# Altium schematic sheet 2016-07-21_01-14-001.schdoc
size 331 x 152 mm; SheetNumber: 1; SheetTotal: 1
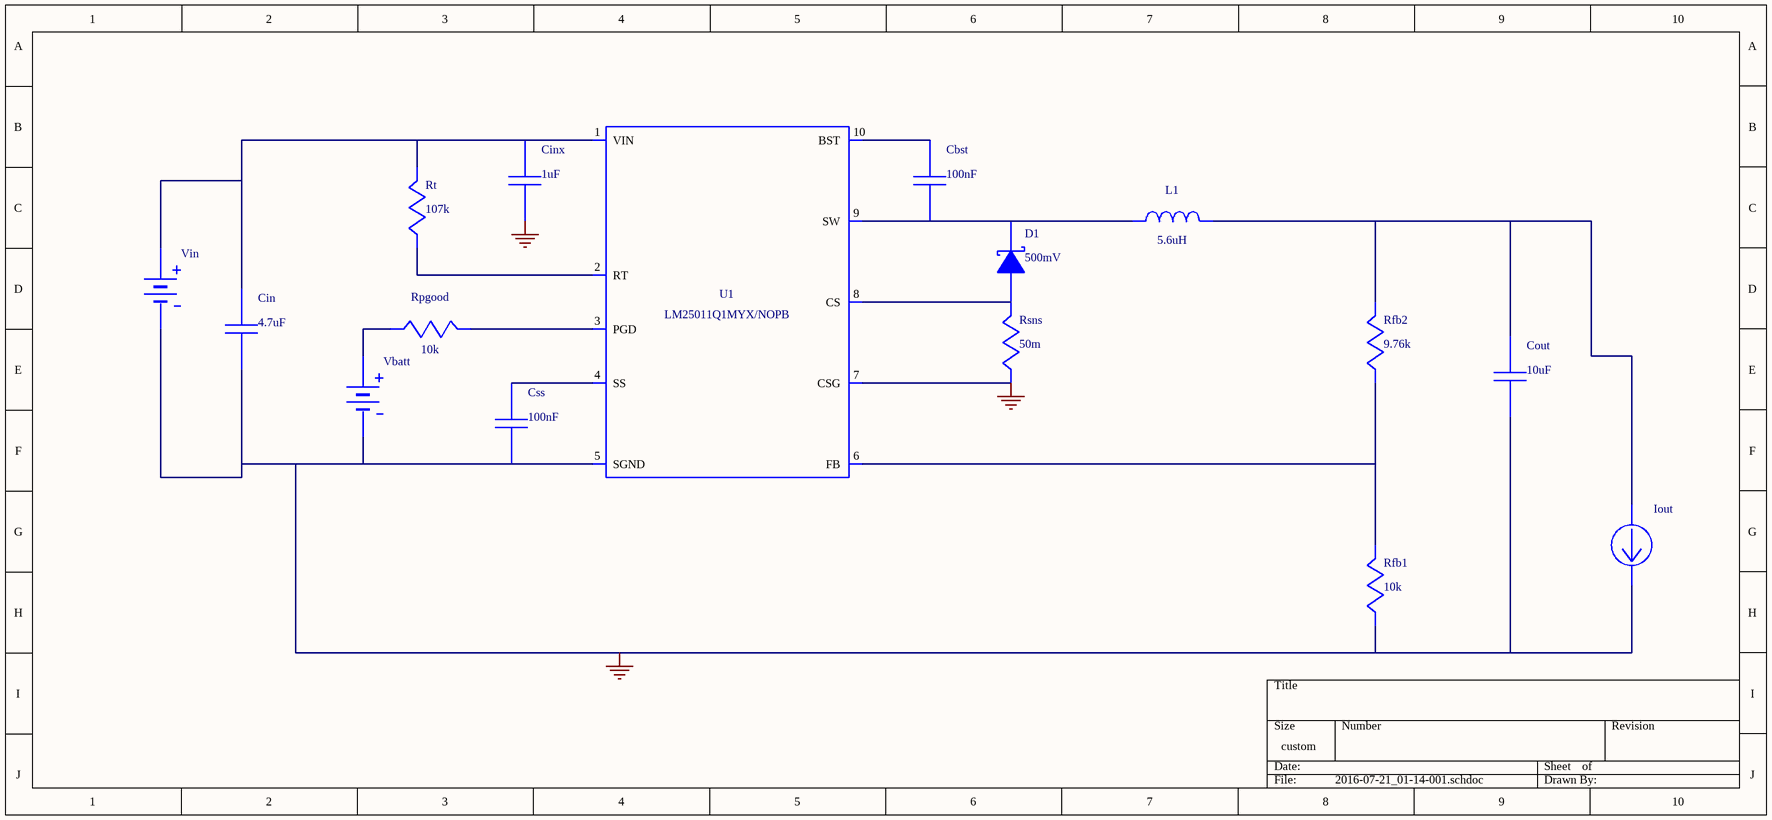
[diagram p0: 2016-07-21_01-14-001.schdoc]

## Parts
Cbst  value 100nF  (hidden comment: GRM21BR71E104KA01L)
Cin  value 4.7uF  (hidden comment: GRM31CR71H475KA12L)
Cinx  value 1uF  (hidden comment: GMK212B7105KG-T)
Cout  value 10uF  (hidden comment: GRM188R60J106ME47D)
Css  value 100nF  (hidden comment: GRM21BR71E104KA01L)
D1  value 500mV  (hidden comment: B340A-13-F)
Iout  WB_CURRENT_LOAD  (value not drawn)
L1  value 5.6uH  (hidden comment: SDR0805-5R6ML)
Rfb1  value 10k  (hidden comment: CRCW040210K0FKED)
Rfb2  value 9.76k  (hidden comment: CRCW04029K76FKED)
Rpgood  value 10k  (hidden comment: CRCW040210K0FKED)
Rsns  value 50m  (hidden comment: CRM0805-FW-R050ELF)
Rt  value 107k  (hidden comment: CRCW0402107KFKED)
U1  LM25011Q1MYX/NOPB
Vbatt  WB_PRIMITIVE_BATTERY  (value not drawn)
Vin  WB_BATTERY  (value not drawn)

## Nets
0: Cin.2 Cinx.2 Cout.2 Css.2 Iout.2(-) Rfb1.2 Rsns.2 U1.5(SGND) U1.7(CSG) U1.11(DAP) Vbatt.2(-) Vin.2(-)
NetCbst_1: Cbst.1 U1.10(BST)
NetCbst_2: Cbst.2 D1.1(K) L1.1 U1.9(SW)
NetCin_1: Cin.1 Cinx.1 Rt.1 U1.1(VIN) Vin.1(+)
NetCout_1: Cout.1 Iout.1(+) L1.2 Rfb2.1
NetCss_1: Css.1 U1.4(SS)
NetD1_2: D1.2(A) Rsns.1 U1.8(CS)
NetRfb1_1: Rfb1.1 Rfb2.2 U1.6(FB)
NetRpgood_1: Rpgood.1 U1.3(PGD)
NetRpgood_2: Rpgood.2 Vbatt.1(+)
NetRt_2: Rt.2 U1.2(RT)

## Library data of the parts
Cbst Css = GRM21BR71E104KA01L: GRM21BR71E104KA0; Manufacturer Name: MuRata
Cin = GRM31CR71H475KA12L: GRM31CR71H475KA1; Manufacturer Name: MuRata
Cinx = GMK212B7105KG-T: Manufacturer Name: Taiyo Yuden
Cout = GRM188R60J106ME47D: GRM188R60J106ME4; Manufacturer Name: MuRata
D1 = B340A-13-F: Manufacturer Name: Diodes Inc.
L1 = SDR0805-5R6ML: Manufacturer Name: Bourns
Rfb1 Rpgood = CRCW040210K0FKED: Manufacturer Name: Vishay-Dale
Rfb2 = CRCW04029K76FKED: Manufacturer Name: Vishay-Dale
Rsns = CRM0805-FW-R050ELF: CRM0805-FW-R050E; Manufacturer Name: Bourns
Rt = CRCW0402107KFKED: Manufacturer Name: Vishay-Dale
U1 = LM25011Q1MYX/NOPB: LM25011Q1MYX/NOP; Manufacturer Name: Texas Instruments
Vbatt = WB_PRIMITIVE_BATTERY: WB_PRIMITIVE_BAT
